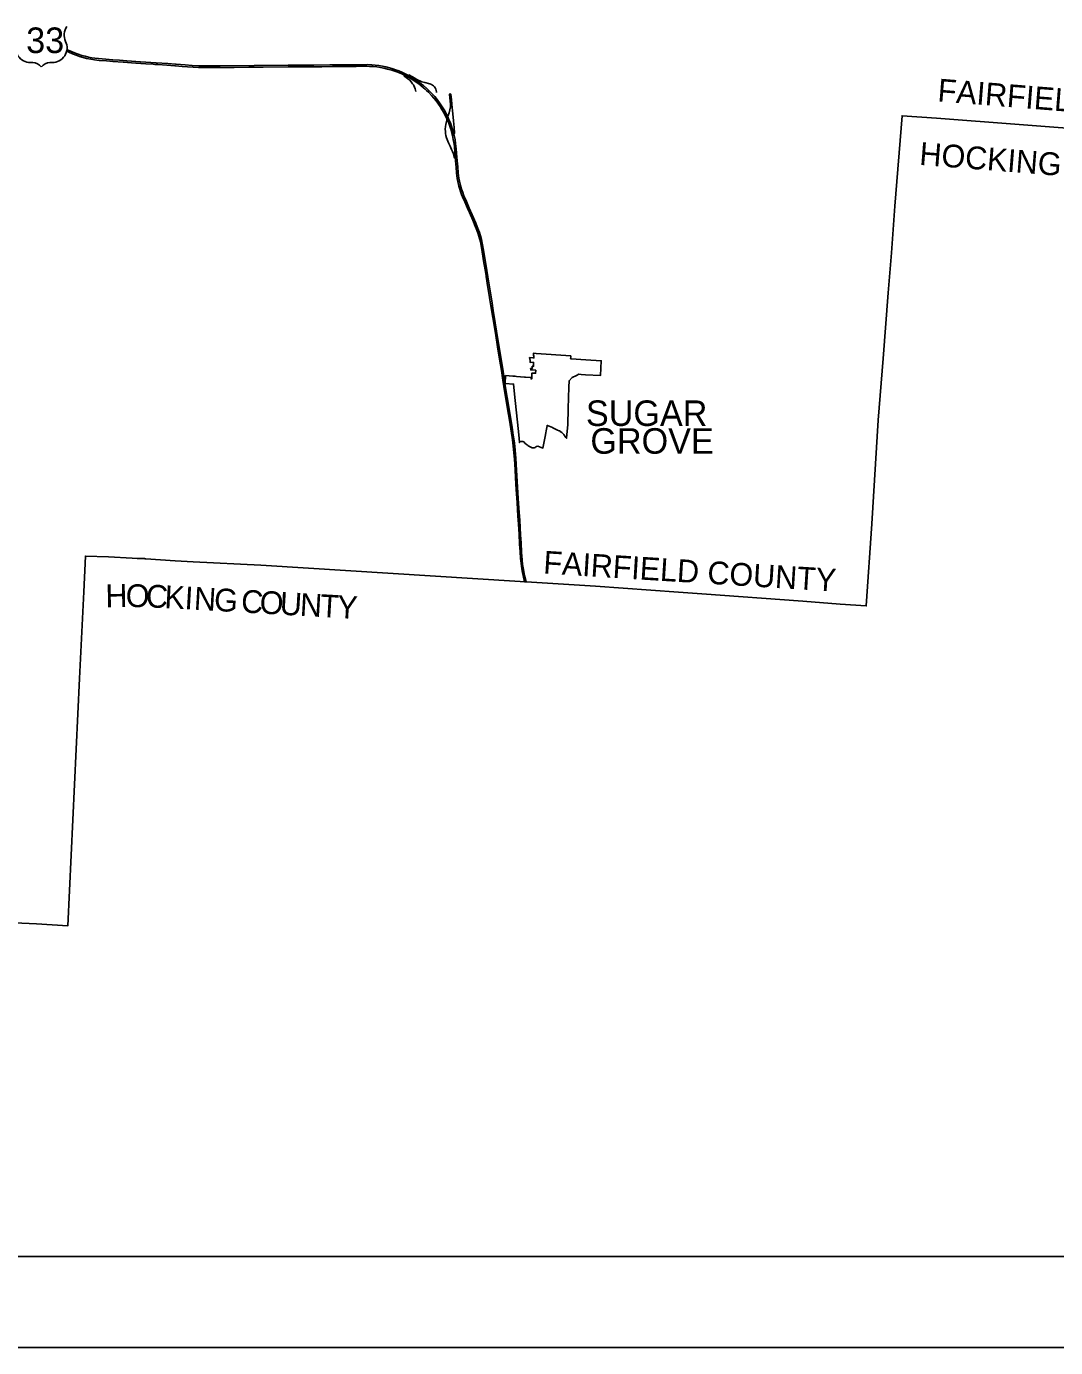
# Model space of a CAD drawing. Extents: x 1801177 to 2073177, y 78841 to 727183.
# Drawn here: x 1932810 to 1977949, y 551183 to 609122 of the extents above; entities that cross this region are included whole.
import ezdxf

# ---------------------------------------------------------------- set-up
doc = ezdxf.new("R2010")
doc.units = 0
for name, color, linetype in [('GM_X_Corporation', 7, 'Continuous'), ('GM_X_Corporation_Text', 7, 'Continuous'), ('GM_X_County', 7, 'Continuous'), ('GM_X_County_Text', 7, 'Continuous'), ('GM_X_US_Location', 7, 'Continuous'), ('GM_X_US_Shield', 7, 'Continuous'), ('SH_Border', 7, 'Continuous'), ('SH_Cut_Line', 7, 'Continuous'), ('UT_P_Electric', 7, 'Continuous')]:
    doc.layers.add(name, color=color, linetype=linetype)

msp = doc.modelspace()

# ---------------------------------------------------------------- linework, layer by layer
at = {"layer": 'GM_X_Corporation'}
msp.add_lwpolyline([(1956684, 594622), (1956679, 594553), (1956701, 594551), (1957343, 594505), (1958025, 594457), (1957982, 593812), (1957338, 593850), (1957137, 593861), (1957036, 593867), (1956937, 593820), (1956749, 593729), (1956614, 593581), (1956604, 593297), (1956574, 592361), (1956551, 591654), (1956545, 591521), (1956500, 591060), (1956481, 591079), (1956469, 591092), (1956428, 591153), (1956407, 591184), (1956399, 591196), (1956399, 591197), (1956376, 591229), (1956375, 591230), (1956354, 591255), (1956351, 591259), (1956351, 591260), (1956350, 591261), (1956323, 591287), (1956322, 591288), (1956297, 591310), (1956296, 591311), (1956266, 591334), (1956265, 591335), (1956265, 591335), (1956260, 591339), (1956247, 591346), (1956226, 591360), (1956225, 591361), (1956213, 591367), (1956191, 591380), (1956182, 591385), (1956181, 591386), (1956107, 591422), (1955988, 591478), (1955898, 591519), (1955877, 591529), (1955668, 591624), (1955659, 591628), (1955656, 591629), (1955651, 591603), (1955639, 591540), (1955625, 591467), (1955577, 591222), (1955575, 591212), (1955461, 590628), (1955315, 590687), (1955248, 590718), (1955179, 590696), (1955155, 590680), (1955125, 590659), (1955075, 590641), (1955007, 590640), (1954972, 590646), (1954956, 590649), (1954903, 590678), (1954900, 590680), (1954847, 590716), (1954809, 590744), (1954790, 590758), (1954767, 590773), (1954741, 590791), (1954676, 590853), (1954636, 590894), (1954620, 590901), (1954589, 590916), (1954532, 590923), (1954482, 590912), (1954436, 590874), (1954419, 591046), (1954388, 591354), (1954251, 592712), (1954178, 593434), (1953806, 593459), (1953828, 593808), (1954143, 593784), (1954143, 593784), (1954243, 593777), (1954302, 593772), (1954662, 593745), (1954669, 593745), (1954685, 593744), (1954696, 593743), (1954925, 593728), (1954937, 593727), (1954949, 593727), (1954944, 593671), (1954943, 593662), (1954974, 593660), (1954974, 593730), (1954982, 593729), (1954979, 593918), (1955046, 593915), (1955123, 593912), (1955140, 593911), (1955146, 594042), (1955146, 594047), (1955139, 594048), (1955129, 594048), (1954964, 594055), (1954933, 594056), (1954923, 594117), (1954954, 594116), (1954982, 594115), (1955003, 594115), (1954999, 594162), (1954994, 594218), (1955055, 594222), (1955053, 594268), (1955052, 594290), (1955051, 594328), (1955048, 594391), (1954911, 594382), (1954898, 594478), (1954881, 594600), (1955017, 594589), (1955070, 594585), (1955066, 594642), (1955062, 594685), (1955049, 594686), (1955048, 594776), (1955047, 594786), (1955170, 594779), (1956687, 594671)], close=True, dxfattribs=at)
at = {"layer": 'GM_X_County'}
msp.add_lwpolyline([(1979976, 604550), (1972730, 605097), (1971219, 605206), (1970906, 601233), (1970746, 599200), (1970607, 597434), (1970381, 594566), (1970168, 591859), (1969897, 587314), (1969642, 583712), (1968499, 583785), (1966869, 583919), (1962432, 584235), (1961415, 584313), (1957763, 584574), (1954728, 584764), (1954661, 584769), (1954473, 584784), (1943089, 585493), (1940125, 585646), (1939331, 585693), (1938045, 585775), (1938023, 585779), (1937982, 585785), (1937673, 585792), (1937448, 585804), (1936417, 585866), (1935401, 585895), (1935326, 584328), (1935144, 580525), (1934624, 569677), (1933259, 569762), (1929351, 569937)], dxfattribs=at)
at = {"layer": 'GM_X_US_Shield'}
for p, q in [((1932997, 607535), (1933090, 607535)), ((1933838, 607535), (1933931, 607535))]:
    msp.add_line(p, q, dxfattribs=at)
for centre, radius, start, end in [((1935120, 608747), 654, 144.99907, 205.45288), ((1932990, 608188), 654, 154.83192, 270.63826), ((1933938, 608188), 654, 269.36174, 25.16808), ((1933090, 607068), 467, 36.8699, 90), ((1933838, 607068), 467, 90, 143.1301)]:
    msp.add_arc(centre, radius, start, end, dxfattribs=at)
at = {"layer": 'SH_Border'}
msp.add_lwpolyline([(1813177, 723183), (2069177, 723183), (2069177, 555183), (1813177, 555183)], close=True, dxfattribs=at)
at = {"layer": 'SH_Cut_Line'}
msp.add_lwpolyline([(1801177, 551183), (2073177, 551183), (2073177, 727183), (1801177, 727183)], close=True, dxfattribs=at)
at = {"layer": 'UT_P_Electric'}
for points in [[(1934574, 608036), (1934664, 607993), (1934836, 607916), (1934987, 607859), (1935133, 607809), (1935293, 607762), (1935452, 607721), (1935639, 607682), (1935796, 607658), (1936004, 607634), (1936323, 607610), (1936602, 607590), (1937048, 607558), (1937607, 607516), (1938045, 607486), (1938374, 607462), (1938438, 607457), (1938567, 607448), (1938973, 607417), (1939323, 607393), (1939344, 607392), (1939635, 607369), (1939881, 607352), (1940125, 607335), (1940352, 607324), (1940592, 607316), (1940797, 607314), (1940992, 607318), (1941228, 607320)], [(1934588, 608112), (1934635, 608088), (1934810, 608008), (1934925, 607961), (1935073, 607906), (1935236, 607854), (1935387, 607813), (1935528, 607779), (1935678, 607751), (1935813, 607730), (1935977, 607710), (1936295, 607685), (1936597, 607663), (1936892, 607645), (1937215, 607619), (1937808, 607576), (1938505, 607525), (1939008, 607490), (1939347, 607465), (1939381, 607462), (1939769, 607436), (1940078, 607413), (1940370, 607399), (1940695, 607390), (1941055, 607392), (1941307, 607396)], [(1941228, 607320), (1941286, 607320), (1941372, 607320), (1941442, 607321), (1941923, 607325), (1942566, 607331), (1943194, 607335), (1944291, 607344), (1944799, 607349), (1945769, 607357), (1946238, 607361), (1946635, 607365), (1947069, 607369), (1947267, 607369), (1947506, 607373), (1947743, 607373), (1947860, 607371), (1948020, 607359), (1948179, 607345), (1948335, 607319), (1948490, 607290), (1948646, 607255), (1948839, 607201), (1949008, 607145), (1949171, 607084), (1949307, 607022), (1949398, 606979)], [(1941307, 607396), (1944288, 607420), (1945423, 607430), (1946121, 607435), (1946881, 607440), (1947487, 607445), (1947763, 607446), (1947956, 607438), (1948107, 607425), (1948270, 607405), (1948421, 607379), (1948577, 607347), (1948732, 607307), (1948884, 607262), (1948999, 607225), (1949148, 607170), (1949305, 607104), (1949450, 607033), (1949573, 606971)], [(1949398, 606979), (1949377, 606942), (1949465, 606886), (1949545, 606824), (1949621, 606763), (1949689, 606688), (1949750, 606606), (1949783, 606556)], [(1949398, 606979), (1949472, 606941), (1949567, 606890), (1949689, 606823), (1949802, 606752), (1949911, 606678), (1950020, 606602), (1950120, 606523), (1950213, 606448), (1950301, 606371), (1950357, 606319), (1950441, 606235)], [(1950798, 606218), (1950792, 606257), (1950767, 606372), (1950741, 606426), (1950704, 606479), (1950670, 606514), (1950628, 606549), (1950579, 606579), (1950501, 606602), (1950285, 606659), (1950152, 606699), (1950065, 606731), (1949995, 606762), (1949931, 606801), (1949848, 606851), (1949590, 606992), (1949573, 606971)], [(1949573, 606971), (1949863, 606800), (1949971, 606726), (1950047, 606670), (1950144, 606597), (1950232, 606528), (1950364, 606411), (1950510, 606271), (1950549, 606230), (1950717, 606051), (1950826, 605913), (1950929, 605776), (1951019, 605643), (1951128, 605467), (1951216, 605308), (1951289, 605151), (1951344, 605032), (1951404, 604889), (1951490, 604643), (1951546, 604437)], [(1949783, 606556), (1949799, 606530), (1949833, 606452), (1949855, 606391), (1949868, 606330), (1949888, 606272)], [(1950441, 606235), (1950580, 606094), (1950681, 605975), (1950781, 605852), (1950879, 605720), (1950958, 605604), (1951034, 605484), (1951107, 605356), (1951262, 605055), (1951330, 604873), (1951381, 604743), (1951421, 604620), (1951472, 604439), (1951484, 604387)], [(1951396, 606178), (1951371, 606148), (1951400, 605842), (1951407, 605708), (1951403, 605599), (1951387, 605471), (1951348, 605328), (1951315, 605215), (1951289, 605151), (1951262, 605055), (1951248, 605006), (1951225, 604892), (1951206, 604823), (1951189, 604730), (1951182, 604623), (1951186, 604513), (1951193, 604430), (1951208, 604341), (1951235, 604241), (1951263, 604162), (1951328, 604014), (1951394, 603874), (1951457, 603732), (1951495, 603633), (1951538, 603532), (1951558, 603466), (1951583, 603365), (1951621, 603377)], [(1951473, 605701), (1951470, 605728), (1951454, 605907), (1951421, 606152), (1951396, 606178)], [(1951546, 604437), (1951588, 604441), (1951566, 604689), (1951536, 604983), (1951510, 605287), (1951473, 605701)], [(1951484, 604387), (1951494, 604345), (1951534, 604161), (1951564, 603965), (1951579, 603850), (1951621, 603377)], [(1951546, 604437), (1951569, 604343), (1951609, 604159), (1951635, 603971), (1951657, 603750), (1951692, 603375), (1951730, 602958), (1951751, 602708), (1951779, 602474), (1951800, 602333), (1951852, 602141), (1951888, 601987), (1951945, 601837), (1952001, 601695), (1952110, 601443), (1952234, 601155), (1952358, 600864), (1952518, 600495), (1952613, 600267), (1952679, 600086), (1952725, 599937), (1952768, 599777), (1952818, 599543), (1952857, 599308), (1952930, 598862), (1952969, 598609), (1953046, 598136), (1953144, 597523), (1953216, 597085), (1953284, 596663), (1953327, 596394), (1953370, 596123), (1953387, 596016)], [(1951621, 603377), (1951659, 602954), (1951680, 602697), (1951707, 602448), (1951727, 602315), (1951771, 602115), (1951827, 601934), (1951831, 601924)], [(1951831, 601924), (1951897, 601756), (1951943, 601644), (1952035, 601428), (1952155, 601148), (1952238, 600960)], [(1952238, 600960), (1952389, 600619), (1952498, 600368), (1952569, 600186), (1952628, 600020), (1952688, 599822), (1952724, 599673), (1952756, 599505), (1952784, 599340), (1952862, 598837), (1952925, 598451), (1952973, 598181)], [(1952973, 598181), (1952979, 598150), (1953055, 597680), (1953110, 597341), (1953141, 597134), (1953198, 596785), (1953266, 596356), (1953323, 596014), (1953325, 596004)], [(1953325, 596004), (1953380, 595664), (1953474, 595073), (1953562, 594536), (1953642, 594031), (1953711, 593606), (1953754, 593337), (1953827, 592877), (1953914, 592356), (1953992, 591861), (1954085, 591288)], [(1953387, 596016), (1953397, 595955), (1953475, 595480), (1953571, 594880), (1953626, 594533), (1953714, 593994), (1953763, 593681), (1953814, 593365), (1953897, 592852), (1953980, 592330), (1954052, 591900), (1954108, 591550), (1954150, 591299)], [(1954085, 591288), (1954130, 590990), (1954162, 590731), (1954195, 590415), (1954217, 590149), (1954231, 589918), (1954245, 589681), (1954266, 589330), (1954297, 588820), (1954333, 588237), (1954369, 587645), (1954392, 587289), (1954417, 586860), (1954443, 586422), (1954463, 586096), (1954485, 585793), (1954507, 585578), (1954540, 585341), (1954573, 585169), (1954597, 585047), (1954662, 584766)], [(1954150, 591299), (1954215, 590846), (1954248, 590537), (1954278, 590182), (1954294, 589912), (1954325, 589416), (1954356, 588913), (1954385, 588424), (1954411, 588002), (1954446, 587453), (1954483, 586825), (1954505, 586469), (1954531, 586044), (1954555, 585736), (1954574, 585532), (1954611, 585307), (1954663, 585047), (1954730, 584761)]]:
    msp.add_lwpolyline(points, dxfattribs=at)

# ---------------------------------------------------------------- texts
at = {"layer": 'GM_X_Corporation_Text'}
for s, p in [('SUGAR', (1957352, 591600)), ('GROVE', (1957546, 590383))]:
    msp.add_text(s, height=1120, rotation=0.00001, dxfattribs=at).set_placement(p)
at = {"layer": 'GM_X_County_Text'}
for s, rotation, p in [('FAIRFIELD COUNTY', 355.46053, (1972751, 605838)), ('HOCKING COUNTY', 355.51045, (1971952, 603053)), ('FAIRFIELD COUNTY', 356.44795, (1955462, 585130)), ('H', 1.18861, (1936285, 583648)), ('O', 358.73199, (1937158, 583667)), ('C', 357.71213, (1938037, 583647)), ('K', 356.97672, (1938847, 583615)), ('I', 356.76913, (1939729, 583568)), ('N', 356.70119, (1940138, 583545)), ('G', 356.68922, (1941020, 583494)), ('C', 356.69013, (1942207, 583426)), ('O', 356.68922, (1943019, 583379)), ('U', 356.69068, (1943902, 583328)), ('N', 356.69031, (1944785, 583277)), ('T', 356.6888, (1945668, 583226)), ('Y', 356.69082, (1946415, 583182))]:
    msp.add_text(s, height=1000, rotation=rotation, dxfattribs=at).set_placement(p)
at = {"layer": 'GM_X_US_Location'}
msp.add_text('33', height=1, rotation=0.00001, dxfattribs=at).set_placement((1933061, 608515))
for s in ['0', '/']:
    msp.add_text(s, height=1, dxfattribs=at).set_placement((1933267, 608722))
at = {"layer": 'GM_X_US_Shield'}
msp.add_text('33', height=1120.7, dxfattribs=at).set_placement((1932799, 607955))

doc.saveas('drawing.dxf')
